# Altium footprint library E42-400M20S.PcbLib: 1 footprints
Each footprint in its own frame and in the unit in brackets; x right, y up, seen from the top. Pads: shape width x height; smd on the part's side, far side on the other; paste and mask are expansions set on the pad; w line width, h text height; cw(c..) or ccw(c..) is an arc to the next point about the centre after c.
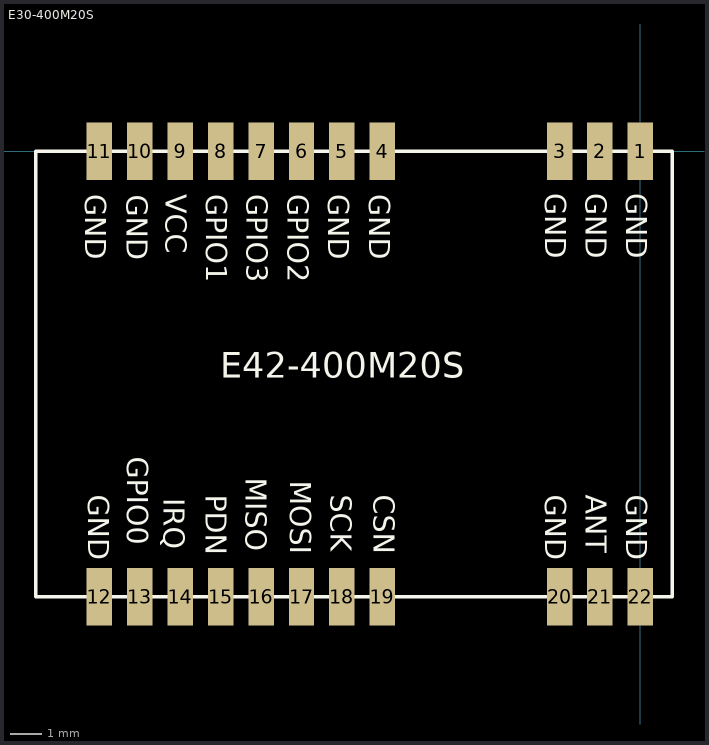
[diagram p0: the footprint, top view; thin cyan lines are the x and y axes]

## E30-400M20S [mm] "20mm*14mm*2.8mm-S"
pads (22):
  rect 0.8x1.8 smd: 1(0,0) 2(-1.27,0) 3(-2.54,0) 4(-8.11,0) 5(-9.38,0) 6(-10.65,0) 7(-11.92,0) 8(-13.19,0) 9(-14.46,0) 10(-15.73,0) 11(-17,0) 12(-17,-14) 13(-15.73,-14) 14(-14.46,-14) 15(-13.19,-14) 16(-11.92,-14) 17(-10.65,-14) 18(-9.38,-14) 19(-8.11,-14) 20(-2.54,-14) 21(-1.27,-14) 22(0,-14)
Top Overlay:
  lines w0.1: -19,-14 -19,0 1,0 1,-14 -19,-14
  text "GND" at -8.528,-1.353 h0.65
  text "GND" at -9.807,-1.353 h0.65
  text "GPIO2" at -11.086,-1.353 h0.65
  text "GPIO3" at -12.364,-1.353 h0.65
  text "GPIO1" at -13.643,-1.353 h0.65
  text "VCC" at -14.922,-1.353 h0.65
  text "GND" at -16.14,-1.373 h0.65
  text "GND" at -17.45,-1.353 h0.65
  text "GND" at -2.996,-1.323 h0.65
  text "GND" at -1.717,-1.323 h0.65
  text "GND" at -0.438,-1.323 h0.65
  text "GND" at -0.438,-10.795 h0.65
  text "ANT" at -1.717,-10.795 h0.65
  text "GND" at -2.996,-10.795 h0.65
  text "GND" at -17.349,-10.795 h0.65
  text "GPIO0" at -16.129,-9.604 h0.65
  text "IRQ" at -14.986,-10.903 h0.65
  text "PDN" at -13.666,-10.795 h0.65
  text "MISO" at -12.396,-10.254 h0.65
  text "MOSI" at -10.999,-10.362 h0.65
  text "SCK" at -9.729,-10.795 h0.65
  text "CSN" at -8.382,-10.795 h0.65
  text "E42-400M20S" at -13.208,-7.112 h0.8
